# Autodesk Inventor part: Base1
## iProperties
Created: 2010-08
Part Number: Base1
Document SubType Name: Modeling
Designer: nguyenducthang
Density: 1 g/cm^3
Mass: 16.0752 g
Surface Area: 62.0517 cm^2
Volume: 16.0752 cm^3
Author: nguyenducthang
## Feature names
1. Extrusion43
2. Chamfer16
